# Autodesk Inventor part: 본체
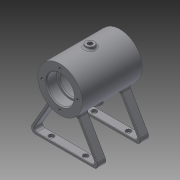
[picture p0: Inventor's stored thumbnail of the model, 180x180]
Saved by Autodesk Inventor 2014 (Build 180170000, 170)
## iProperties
Created: 2016-03
Part Number: 본체
Material: 일반
Document SubType Name: Modeling
Designer: basic
Density: 1 g/cm^3
Appearance: 기본값
Author: basic
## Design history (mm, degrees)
sketch "스케치1"
  geometry: C1 r 26 at (0, 0); 1 further point
  constraints: 1 centre point, 1 coincident
  dimensions: "d0" = 52 diameter of C1
extrude "돌출1" new body sketch "스케치1" distance "d1" = 70; taper "d2" = 0 deg
sketch "스케치2"
  geometry: L1 (26, 70)-(26, 0) reference; L2 (26, 0)-(-26, 0) reference; L3 (-26, 0)-(-26, 70) reference; L4 (-26, 70)-(26, 70) reference; L5 (0, 70)-(0, 0); L6 (16, 70)-(16, 58); L7 (16, 58)-(14, 58); L8 (14, 58)-(14, 56); L9 (14, 56)-(21, 56); L10 (21, 56)-(21, 14); L11 (21, 14)-(14, 14); L12 (14, 14)-(14, 12); L13 (14, 12)-(16, 12); L14 (16, 12)-(16, 0); L15 (26, 35)-(-26, 35)
  constraints: 22 end point, 7 parallel, 3 midpoint, 2 perpendicular, 2 point on line, 1 collinear, 1 other
  dimensions: "d3" = 32 diameter of L6 L5; "d4" = 12 distance between parallel lines of L4 L7; "d5" = 28 diameter of L8 L5; "d7" = 42 distance between parallel lines of L11 L9; "d8" = 12 distance between parallel lines of L2 L13; "d9" = 32 diameter of L14 L5; "d10" = 28 diameter of L12 L5; "d11" = 42 diameter of L10 L5
revolve "회전1" sketch "스케치2" stored, may be unused: angle "d12" = 90 deg
fillet "모깎기1" dims "d13" = 0.3
fillet "모깎기2" dims "d14" = 0.3
node "작업 평면1"
sketch "스케치3"
  geometry: L1 (-16.613, -20)-(-42.594, -65); L2 (-42.594, -65)-(42.594, -65); L3 (42.594, -65)-(16.613, -20); L4 (0, 0)-(0, -65); L5 (-14.183, -21.791)-(-37.398, -62); L6 (-37.398, -62)-(37.398, -62); L7 (37.398, -62)-(14.183, -21.791); C1 r 21 at (0, 0) reference; A1 r 26 centre (0, 0) between (-16.613, -20) and (16.613, -20) reference; 1 further point
  constraints: 14 end point, 4 point on circle, 2 parallel, 2 perpendicular, 1 horizontal, 1 midpoint, 1 other
  dimensions: "d17" = 3 distance between parallel lines of L1 L5; "d18" = 3 distance between parallel lines of L2 L6; "d19" = 3 distance between parallel lines of L3 L7; "d20" = 30 deg angle of L4 L5; "d21" = 30 deg angle of L7 L4 (derived); "d22" = 65 distance from line of L2 point (0, 0); "d23" = 45 distance from line of L2 L3.end
extrude "돌출2" join sketch "스케치3" distance "d24" = 10; taper "d25" = 0 deg
fillet "모깎기3" dims "d26" = 5
fillet "모깎기4" dims "d27" = 3
node "작업 평면3"
node "작업 평면4"
sketch "스케치4"
  geometry: L1 (26, 70)-(-26, 70) reference; C1 r 5 at (0, 35); 2 further points
  constraints: 1 centre point, 1 coincident
  dimensions: "d30" = 35 distance from line of L1 point (0, 35); "d31" = 10 diameter of C1
extrude "돌출3" join sketch "스케치4" distance "d32" = 4; taper "d33" = 0 deg
sketch "스케치5"
  geometry: C1 r 5 at (0, 0) reference; 1 further point
hole "구멍1" sketch "스케치5" at (0, 0) diameter "d34" = 5.188; stored, may be unused: countersink angle "d38" = 90 deg, drill point angle "d40" = 118 deg; dims "d35" = 20, "d36" = 4, "d37" = 2, "d39" = 20
sketch "스케치6"
  geometry: L1 (-5, 25.515)-(-5, 29) reference; L2 (-5, 29)-(-2.594, 29) reference; L3 (-2.594, 29)-(-2.594, 20.839) reference; L4 (2.594, 20.839)-(2.594, 29) reference; L5 (2.594, 29)-(5, 29) reference; L6 (5, 29)-(5, 25.515) reference; L7 (0, 0)-(0, -26); L8 (0, 0)-(7.506, -28.012); A1 r 21 centre (0, 0) between (-2.594, 20.839) and (2.594, 20.839) reference; A2 r 26 centre (0, 0) between (-5, 25.515) and (5, 25.515) reference; 1 further point
  constraints: 4 end point, 1 point on circle
  dimensions: "d42" = 15 deg angle of L7 L8; "d43" = 29 distance of L7.start L8.end
  node "절단 모서리 투영3"
node "작업 평면5"
sketch "스케치7"
  geometry: C1 r 6 at (0, 0); 1 further point
  constraints: 1 centre point
  dimensions: "d44" = 12 diameter of C1
extrude "돌출4" join sketch "스케치7" distance "d45" = 4; taper "d46" = 0 deg
sketch "스케치8"
  geometry: C1 r 6 at (0, 0) reference; 1 further point
sketch "스케치9"
  geometry: C1 r 6 at (0, 0) reference; 1 further point
hole "구멍2" sketch "스케치9" at (0, 0) diameter "d47" = 5.188; stored, may be unused: countersink angle "d51" = 90 deg, drill point angle "d53" = 118 deg; dims "d48" = 20, "d49" = 4, "d50" = 2, "d52" = 20
chamfer "모따기1" distance "d54" = 1; stored, may be unused: second distance "d55" = 2, angle "d56" = 45 deg
sketch "스케치10"
  geometry: L1 (0, -10)-(64.403, -10) reference; L2 (32.202, -10)-(32.202, 55); L3 (-6.315, -10)-(-6.315, 0) reference; L4 (-6.315, 0)-(0, 0) reference; L5 (0, 0)-(0, -10) reference; L6 (64.403, -10)-(0, -10) reference; L7 (64.403, 0)-(64.403, -10) reference; L8 (64.403, 0)-(70.718, 0) reference; L9 (70.718, 0)-(70.718, -10) reference; L10 (70.718, -10)-(64.403, -10) reference; L11 (0, -10)-(-6.315, -10) reference; L12 (0, 0)-(64.403, 0) reference; L13 (-6.315, 40)-(-6.315, 50) reference; L14 (-6.315, 50)-(0, 50) reference; L15 (0, 50)-(0, 40) reference; L16 (64.403, 40)-(0, 40) reference; L17 (64.403, 50)-(64.403, 40) reference; L18 (64.403, 50)-(70.718, 50) reference; L19 (70.718, 50)-(70.718, 40) reference; L20 (70.718, 40)-(64.403, 40) reference; L21 (0, 40)-(-6.315, 40) reference; L22 (0, 50)-(64.403, 50) reference; 4 further points
  constraints: 2 end point, 2 symmetric about line, 1 midpoint, 1 perpendicular
  dimensions: "d59" = 40 distance of point (52.202, -5) point (12.202, -5); "d60" = 40 distance of point (52.202, 45) point (12.202, 45); "d61" = 20 distance from line of point (12.202, 45) L2 (derived)
hole "구멍3" sketch "스케치10" at (12.202, -5), (52.202, -5), (12.202, 45), (52.202, 45) diameter "d62" = 6; stored, may be unused: countersink angle "d66" = 90 deg, drill point angle "d68" = 118 deg; dims "d63" = 20, "d64" = 4, "d65" = 2, "d67" = 4
fillet "모깎기5" dims "d69" = 0.5
sketch "스케치11" dims "d70" = 42
  geometry: C1 r 17 at (0, 0) reference; 2 further points
  constraints: 1 coincident, 1 vertical alignment, 2 other
hole "구멍4" sketch "스케치11" at (0, 21) diameter "d71" = 3.242; stored, may be unused: countersink angle "d75" = 90 deg, drill point angle "d77" = 118 deg; dims "d72" = 8, "d73" = 4, "d74" = 2, "d76" = 10
node "작업 평면6"
sketch "스케치12"
  geometry: L1 (-26, 0)-(-26, 70) reference; 2 further points
  constraints: 1 other
  dimensions: "d82" = 35 distance of point (0, 0) point (0, 35); "d83" = 26 distance from line of L1 point (0, 35)
feature "엠보싱1" sketch "스케치12" dims "d84" = 0.5, "d85" = 0
fillet "모깎기6" dims "d86" = 2
fillet "모깎기8" dims "d88" = 2, "d89" = 3
node "솔리드1"
mirror "대칭1"
pattern_circular "원형 패턴1" dims angle "d79" = 360 deg
mirror "대칭2"
node "절단 모서리 투영1"
node "절단 모서리 투영2"
node "절단 모서리 투영4"
other parameters: "d15" = 15, "d28" = 35, "d29" = 29, "d81" = -27
